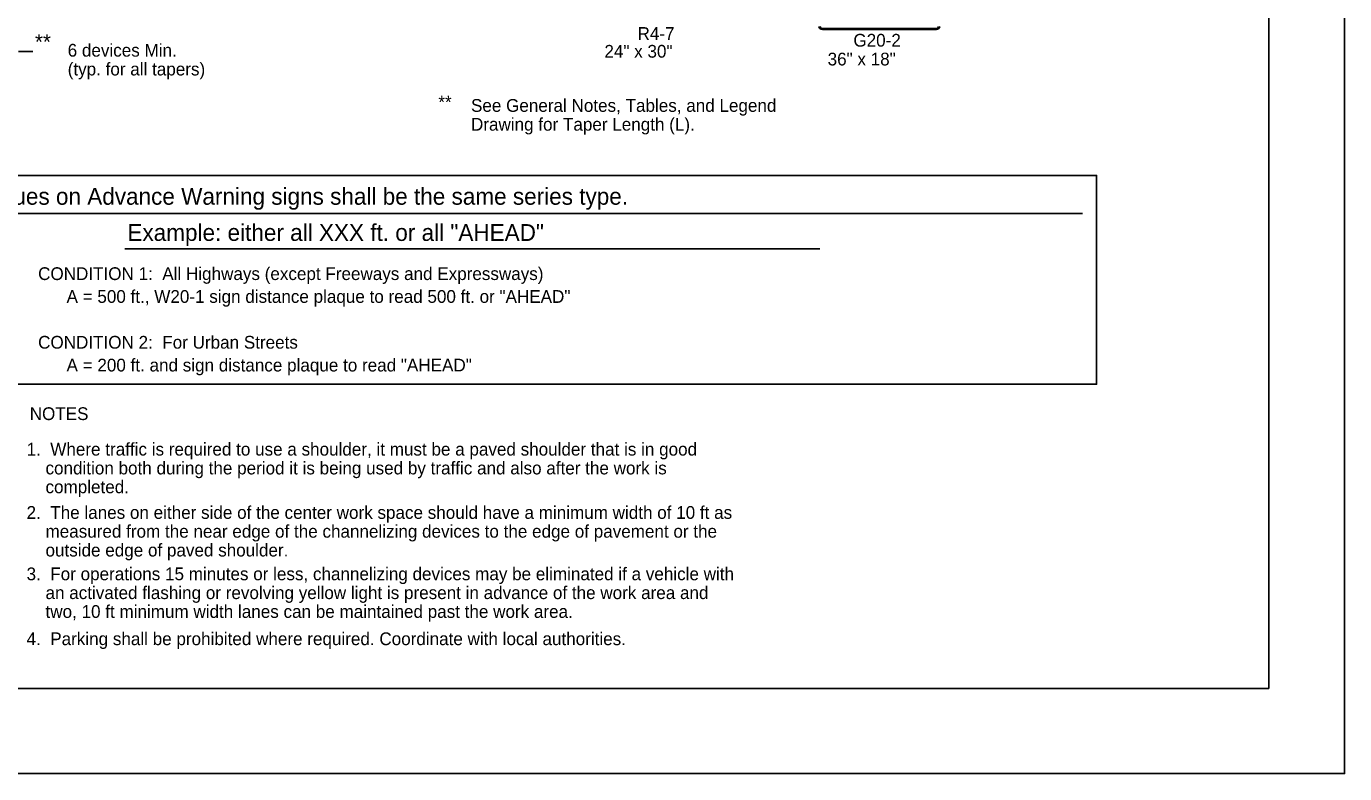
# Model space of a CAD drawing. Extents: x -14145 to -13521, y 30244 to 30661.
# Drawn here: x -13778.87 to -13757.17, y 30532.81 to 30545.11 of the extents above; entities that cross this region are included whole.
import ezdxf

# ---------------------------------------------------------------- set-up
doc = ezdxf.new("R2010")
doc.units = 0
for name, color, linetype in [('1', 7, 'Continuous'), ('10', 7, 'Continuous'), ('2', 7, 'Continuous'), ('61', 7, 'Continuous')]:
    doc.layers.add(name, color=color, linetype=linetype)

msp = doc.modelspace()

# ---------------------------------------------------------------- linework, layer by layer
at = {"layer": '1'}
for p, q in [((-13765.766, 30545.077), (-13763.893, 30545.077)), ((-13765.766, 30545.062), (-13763.893, 30545.062)), ((-13778.767, 30544.698), (-13779, 30544.698))]:
    msp.add_line(p, q, dxfattribs=at)
for centre, major_axis, ratio, start_param, end_param in [((-13765.768, 30545.113), (0.0609, 0), 0.839899, 3.141593, 4.712389), ((-13765.768, 30545.113), (0, -0.0365), 0.999938, 4.712389, 6.283185), ((-13763.896, 30545.113), (0, 0.0365), 0.999938, 3.141593, 4.712389), ((-13763.896, 30545.113), (-0.0609, 0), 0.839899, 1.570796, 3.141593)]:
    msp.add_ellipse(centre, major_axis=major_axis, ratio=ratio, start_param=start_param, end_param=end_param, dxfattribs=at)
at = {"layer": '10'}
for p, q in [((-13758.422, 30556.777), (-13758.422, 30534.207)), ((-13758.422, 30534.207), (-13789.874, 30534.207))]:
    msp.add_line(p, q, dxfattribs=at)
at = {"layer": '2'}
for p, q in [((-13781.437, 30542.032), (-13761.487, 30542.032)), ((-13777.251, 30541.448), (-13765.814, 30541.448))]:
    msp.add_line(p, q, dxfattribs=at)
msp.add_lwpolyline([(-13781.651, 30542.658), (-13761.256, 30542.658), (-13761.256, 30539.22), (-13781.651, 30539.22)], close=True, dxfattribs=at)
at = {"layer": '61'}
msp.add_lwpolyline([(-13790.174, 30558.307), (-13757.174, 30558.307), (-13757.174, 30532.807), (-13790.174, 30532.807)], close=True, dxfattribs=at)

# ---------------------------------------------------------------- texts
at = {"layer": '1'}
for s, p in [('CONDITION 1:  All Highways (except Freeways and Expressways)', (-13778.678, 30540.936)), ('      A = 500 ft., W20-1 sign distance plaque to read 500 ft. or "AHEAD"', (-13778.678, 30540.56)), ('CONDITION 2:  For Urban Streets', (-13778.678, 30539.806)), ('      A = 200 ft. and sign distance plaque to read "AHEAD"', (-13778.678, 30539.43))]:
    msp.add_text(s, height=0.21, dxfattribs=at).set_placement(p)
at = {"layer": '2'}
for s, height, p in [('**', 0.252, (-13778.73, 30544.732)), ('R4-7', 0.21, (-13768.812, 30544.891)), ('G20-2', 0.21, (-13765.259, 30544.78)), ('6 devices Min.', 0.21, (-13778.191, 30544.615)), ('24" x 30"', 0.21, (-13769.357, 30544.598)), ('(typ. for all tapers)', 0.21, (-13778.191, 30544.305)), ('36" x 18"', 0.21, (-13765.683, 30544.47)), ('**', 0.21, (-13772.09, 30543.76)), ('See General Notes, Tables, and Legend ', 0.21, (-13771.553, 30543.706)), ('Drawing for Taper Length (L).', 0.21, (-13771.553, 30543.396)), ('Distance plaques on Advance Warning signs shall be the same series type.', 0.2772, (-13781.331, 30542.176)), ('Example: either all XXX ft. or all "AHEAD"', 0.2772, (-13777.208, 30541.58)), ('NOTES', 0.21, (-13778.816, 30538.63)), ('1.  Where traffic is required to use a shoulder, it must be a paved shoulder that is in good', 0.21, (-13778.868, 30538.045)), ('    condition both during the period it is being used by traffic and also after the work is', 0.21, (-13778.868, 30537.735)), ('    completed.', 0.21, (-13778.868, 30537.425)), ('2.  The lanes on either side of the center work space should have a minimum width of 10 ft as ', 0.21, (-13778.868, 30537.003)), ('    measured from the near edge of the channelizing devices to the edge of pavement or the ', 0.21, (-13778.868, 30536.693)), ('    outside edge of paved shoulder.', 0.21, (-13778.868, 30536.383)), ('3.  For operations 15 minutes or less, channelizing devices may be eliminated if a vehicle with', 0.21, (-13778.868, 30535.992)), ('    an activated flashing or revolving yellow light is present in advance of the work area and', 0.21, (-13778.868, 30535.682)), ('    two, 10 ft minimum width lanes can be maintained past the work area.', 0.21, (-13778.868, 30535.372)), ('4.  Parking shall be prohibited where required. Coordinate with local authorities.', 0.21, (-13778.868, 30534.923))]:
    msp.add_text(s, height=height, dxfattribs=at).set_placement(p)

doc.saveas('drawing.dxf')
